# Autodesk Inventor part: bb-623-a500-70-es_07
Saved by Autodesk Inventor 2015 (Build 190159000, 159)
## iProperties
Created: 2022-04
Part Number: bb-623-a500-70-es_07
Checked By: TraceParts S.A.
Material: Generic
Catalog Web Link: www.traceparts.com
Document SubType Name: Modeling
Designer: TraceParts
Density: 1 g/cm^3
Appearance: Default
Company: TraceParts S.A.
Author: TraceParts
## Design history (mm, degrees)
feature "bb-623-a500-70-es_07.ipt"
body "Solid1"
